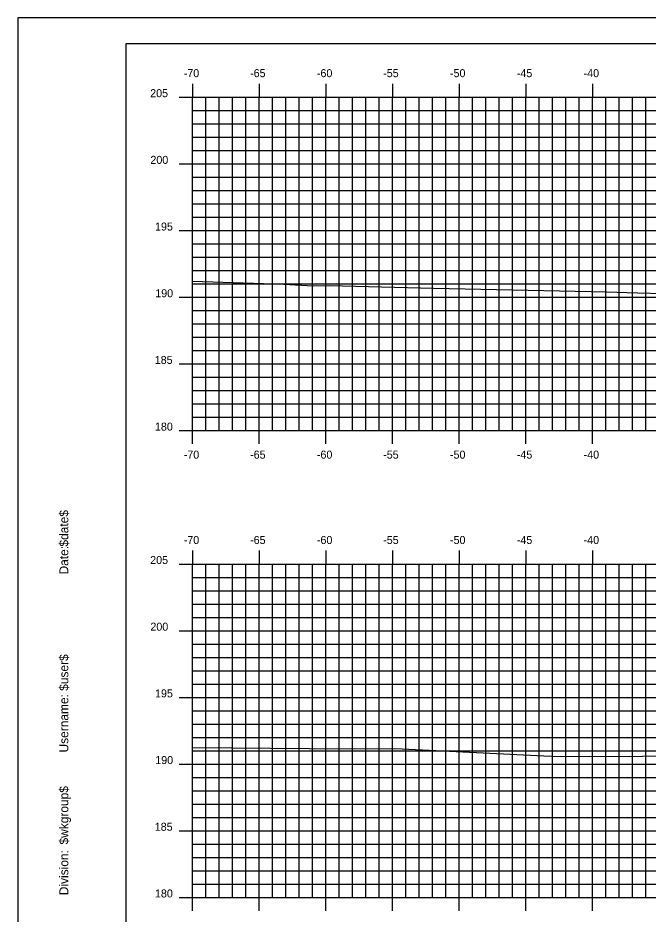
# Model space of a CAD drawing. Extents: x 1723543 to 1723714, y 458501 to 458611.
# Drawn here: x 1723542.7 to 1723589.9, y 458544 to 458611.2 of the extents above; entities that cross this region are included whole.
import ezdxf

# ---------------------------------------------------------------- set-up
doc = ezdxf.new("R2010")
doc.units = 0
for name, color, linetype in [('BORDER', 7, 'Continuous'), ('H_V ANNOTATION', 7, 'Continuous'), ('MAJOR', 7, 'Continuous'), ('MINOR', 7, 'Continuous'), ('PLOT BOUNDARY', 7, 'Continuous'), ('S_Roadway_Centerline', 7, 'Continuous')]:
    doc.layers.add(name, color=color, linetype=linetype)

msp = doc.modelspace()

# ---------------------------------------------------------------- linework, layer by layer
at = {"layer": 'BORDER'}
msp.add_lwpolyline([(1723550.786, 458504.254), (1723710.786, 458504.254), (1723710.786, 458609.254), (1723550.786, 458609.254)], close=True, dxfattribs=at)
at = {"layer": 'MAJOR'}
for p, q in [((1723555.785, 458606.256), (1723555.785, 458605.254)), ((1723560.785, 458606.256), (1723560.785, 458605.254)), ((1723565.785, 458606.256), (1723565.785, 458605.254)), ((1723570.785, 458606.256), (1723570.785, 458605.254)), ((1723575.785, 458606.256), (1723575.785, 458605.254)), ((1723580.785, 458606.256), (1723580.785, 458605.254)), ((1723585.785, 458606.256), (1723585.785, 458605.254)), ((1723554.783, 458605.254), (1723555.785, 458605.254)), ((1723555.785, 458605.254), (1723695.785, 458605.254)), ((1723555.785, 458580.254), (1723555.785, 458605.254)), ((1723555.785, 458580.254), (1723555.785, 458605.254)), ((1723555.785, 458605.254), (1723695.785, 458605.254)), ((1723560.785, 458580.254), (1723560.785, 458605.254)), ((1723565.785, 458580.254), (1723565.785, 458605.254)), ((1723570.785, 458580.254), (1723570.785, 458605.254)), ((1723575.785, 458580.254), (1723575.785, 458605.254)), ((1723580.785, 458580.254), (1723580.785, 458605.254)), ((1723585.785, 458580.254), (1723585.785, 458605.254)), ((1723554.783, 458600.254), (1723555.785, 458600.254)), ((1723555.785, 458600.254), (1723695.785, 458600.254)), ((1723554.783, 458595.254), (1723555.785, 458595.254)), ((1723555.785, 458595.254), (1723695.785, 458595.254)), ((1723554.783, 458590.254), (1723555.785, 458590.254)), ((1723555.785, 458590.254), (1723695.785, 458590.254)), ((1723554.783, 458585.254), (1723555.785, 458585.254)), ((1723555.785, 458585.254), (1723695.785, 458585.254)), ((1723554.783, 458580.254), (1723555.785, 458580.254)), ((1723555.785, 458580.254), (1723695.785, 458580.254)), ((1723555.785, 458580.254), (1723695.785, 458580.254)), ((1723555.785, 458579.252), (1723555.785, 458580.254)), ((1723560.785, 458579.252), (1723560.785, 458580.254)), ((1723565.785, 458579.252), (1723565.785, 458580.254)), ((1723570.785, 458579.252), (1723570.785, 458580.254)), ((1723575.785, 458579.252), (1723575.785, 458580.254)), ((1723580.785, 458579.252), (1723580.785, 458580.254)), ((1723585.785, 458579.252), (1723585.785, 458580.254)), ((1723555.785, 458571.256), (1723555.785, 458570.254)), ((1723560.785, 458571.256), (1723560.785, 458570.254)), ((1723565.785, 458571.256), (1723565.785, 458570.254)), ((1723570.785, 458571.256), (1723570.785, 458570.254)), ((1723575.785, 458571.256), (1723575.785, 458570.254)), ((1723580.785, 458571.256), (1723580.785, 458570.254)), ((1723585.785, 458571.256), (1723585.785, 458570.254)), ((1723554.783, 458570.254), (1723555.785, 458570.254)), ((1723555.785, 458570.254), (1723695.785, 458570.254)), ((1723555.785, 458545.254), (1723555.785, 458570.254)), ((1723555.785, 458545.254), (1723555.785, 458570.254)), ((1723555.785, 458570.254), (1723695.785, 458570.254)), ((1723560.785, 458545.254), (1723560.785, 458570.254)), ((1723565.785, 458545.254), (1723565.785, 458570.254)), ((1723570.785, 458545.254), (1723570.785, 458570.254)), ((1723575.785, 458545.254), (1723575.785, 458570.254)), ((1723580.785, 458545.254), (1723580.785, 458570.254)), ((1723585.785, 458545.254), (1723585.785, 458570.254)), ((1723554.783, 458565.254), (1723555.785, 458565.254)), ((1723555.785, 458565.254), (1723695.785, 458565.254)), ((1723554.783, 458560.254), (1723555.785, 458560.254)), ((1723555.785, 458560.254), (1723695.785, 458560.254)), ((1723554.783, 458555.254), (1723555.785, 458555.254)), ((1723555.785, 458555.254), (1723695.785, 458555.254)), ((1723554.783, 458550.254), (1723555.785, 458550.254)), ((1723555.785, 458550.254), (1723695.785, 458550.254)), ((1723554.783, 458545.254), (1723555.785, 458545.254)), ((1723555.785, 458545.254), (1723695.785, 458545.254)), ((1723555.785, 458545.254), (1723695.785, 458545.254)), ((1723555.785, 458544.252), (1723555.785, 458545.254)), ((1723560.785, 458544.252), (1723560.785, 458545.254)), ((1723565.785, 458544.252), (1723565.785, 458545.254)), ((1723570.785, 458544.252), (1723570.785, 458545.254)), ((1723575.785, 458544.252), (1723575.785, 458545.254)), ((1723580.785, 458544.252), (1723580.785, 458545.254)), ((1723585.785, 458544.252), (1723585.785, 458545.254))]:
    msp.add_line(p, q, dxfattribs=at)
at = {"layer": 'MINOR'}
for p, q in [((1723556.785, 458580.254), (1723556.785, 458605.254)), ((1723557.785, 458580.254), (1723557.785, 458605.254)), ((1723558.785, 458580.254), (1723558.785, 458605.254)), ((1723559.785, 458580.254), (1723559.785, 458605.254)), ((1723561.785, 458580.254), (1723561.785, 458605.254)), ((1723562.785, 458580.254), (1723562.785, 458605.254)), ((1723563.785, 458580.254), (1723563.785, 458605.254)), ((1723564.785, 458580.254), (1723564.785, 458605.254)), ((1723566.785, 458580.254), (1723566.785, 458605.254)), ((1723567.785, 458580.254), (1723567.785, 458605.254)), ((1723568.785, 458580.254), (1723568.785, 458605.254)), ((1723569.785, 458580.254), (1723569.785, 458605.254)), ((1723571.785, 458580.254), (1723571.785, 458605.254)), ((1723572.785, 458580.254), (1723572.785, 458605.254)), ((1723573.785, 458580.254), (1723573.785, 458605.254)), ((1723574.785, 458580.254), (1723574.785, 458605.254)), ((1723576.785, 458580.254), (1723576.785, 458605.254)), ((1723577.785, 458580.254), (1723577.785, 458605.254)), ((1723578.785, 458580.254), (1723578.785, 458605.254)), ((1723579.785, 458580.254), (1723579.785, 458605.254)), ((1723581.785, 458580.254), (1723581.785, 458605.254)), ((1723582.785, 458580.254), (1723582.785, 458605.254)), ((1723583.785, 458580.254), (1723583.785, 458605.254)), ((1723584.785, 458580.254), (1723584.785, 458605.254)), ((1723586.785, 458580.254), (1723586.785, 458605.254)), ((1723587.785, 458580.254), (1723587.785, 458605.254)), ((1723588.785, 458580.254), (1723588.785, 458605.254)), ((1723589.785, 458580.254), (1723589.785, 458605.254)), ((1723555.785, 458604.254), (1723695.785, 458604.254)), ((1723555.785, 458604.254), (1723556.787, 458604.254)), ((1723555.785, 458603.254), (1723695.785, 458603.254)), ((1723555.785, 458603.254), (1723556.787, 458603.254)), ((1723555.785, 458602.254), (1723695.785, 458602.254)), ((1723555.785, 458602.254), (1723556.787, 458602.254)), ((1723555.785, 458601.254), (1723695.785, 458601.254)), ((1723555.785, 458601.254), (1723556.787, 458601.254)), ((1723555.785, 458599.254), (1723695.785, 458599.254)), ((1723555.785, 458599.254), (1723556.787, 458599.254)), ((1723555.785, 458598.254), (1723695.785, 458598.254)), ((1723555.785, 458598.254), (1723556.787, 458598.254)), ((1723555.785, 458597.254), (1723695.785, 458597.254)), ((1723555.785, 458597.254), (1723556.787, 458597.254)), ((1723555.785, 458596.254), (1723695.785, 458596.254)), ((1723555.785, 458596.254), (1723556.787, 458596.254)), ((1723555.785, 458594.254), (1723695.785, 458594.254)), ((1723555.785, 458594.254), (1723556.787, 458594.254)), ((1723555.785, 458593.254), (1723695.785, 458593.254)), ((1723555.785, 458593.254), (1723556.787, 458593.254)), ((1723555.785, 458592.254), (1723695.785, 458592.254)), ((1723555.785, 458592.254), (1723556.787, 458592.254)), ((1723555.785, 458591.254), (1723695.785, 458591.254)), ((1723555.785, 458591.254), (1723556.787, 458591.254)), ((1723555.785, 458589.254), (1723695.785, 458589.254)), ((1723555.785, 458589.254), (1723556.787, 458589.254)), ((1723555.785, 458588.254), (1723695.785, 458588.254)), ((1723555.785, 458588.254), (1723556.787, 458588.254)), ((1723555.785, 458587.254), (1723695.785, 458587.254)), ((1723555.785, 458587.254), (1723556.787, 458587.254)), ((1723555.785, 458586.254), (1723695.785, 458586.254)), ((1723555.785, 458586.254), (1723556.787, 458586.254)), ((1723555.785, 458584.254), (1723695.785, 458584.254)), ((1723555.785, 458584.254), (1723556.787, 458584.254)), ((1723555.785, 458583.254), (1723695.785, 458583.254)), ((1723555.785, 458583.254), (1723556.787, 458583.254)), ((1723555.785, 458582.254), (1723695.785, 458582.254)), ((1723555.785, 458582.254), (1723556.787, 458582.254)), ((1723555.785, 458581.254), (1723695.785, 458581.254)), ((1723555.785, 458581.254), (1723556.787, 458581.254)), ((1723556.785, 458545.254), (1723556.785, 458570.254)), ((1723557.785, 458545.254), (1723557.785, 458570.254)), ((1723558.785, 458545.254), (1723558.785, 458570.254)), ((1723559.785, 458545.254), (1723559.785, 458570.254)), ((1723561.785, 458545.254), (1723561.785, 458570.254)), ((1723562.785, 458545.254), (1723562.785, 458570.254)), ((1723563.785, 458545.254), (1723563.785, 458570.254)), ((1723564.785, 458545.254), (1723564.785, 458570.254)), ((1723566.785, 458545.254), (1723566.785, 458570.254)), ((1723567.785, 458545.254), (1723567.785, 458570.254)), ((1723568.785, 458545.254), (1723568.785, 458570.254)), ((1723569.785, 458545.254), (1723569.785, 458570.254)), ((1723571.785, 458545.254), (1723571.785, 458570.254)), ((1723572.785, 458545.254), (1723572.785, 458570.254)), ((1723573.785, 458545.254), (1723573.785, 458570.254)), ((1723574.785, 458545.254), (1723574.785, 458570.254)), ((1723576.785, 458545.254), (1723576.785, 458570.254)), ((1723577.785, 458545.254), (1723577.785, 458570.254)), ((1723578.785, 458545.254), (1723578.785, 458570.254)), ((1723579.785, 458545.254), (1723579.785, 458570.254)), ((1723581.785, 458545.254), (1723581.785, 458570.254)), ((1723582.785, 458545.254), (1723582.785, 458570.254)), ((1723583.785, 458545.254), (1723583.785, 458570.254)), ((1723584.785, 458545.254), (1723584.785, 458570.254)), ((1723586.785, 458545.254), (1723586.785, 458570.254)), ((1723587.785, 458545.254), (1723587.785, 458570.254)), ((1723588.785, 458545.254), (1723588.785, 458570.254)), ((1723589.785, 458545.254), (1723589.785, 458570.254)), ((1723555.785, 458569.254), (1723695.785, 458569.254)), ((1723555.785, 458569.254), (1723556.787, 458569.254)), ((1723555.785, 458568.254), (1723695.785, 458568.254)), ((1723555.785, 458568.254), (1723556.787, 458568.254)), ((1723555.785, 458567.254), (1723695.785, 458567.254)), ((1723555.785, 458567.254), (1723556.787, 458567.254)), ((1723555.785, 458566.254), (1723695.785, 458566.254)), ((1723555.785, 458566.254), (1723556.787, 458566.254)), ((1723555.785, 458564.254), (1723695.785, 458564.254)), ((1723555.785, 458564.254), (1723556.787, 458564.254)), ((1723555.785, 458563.254), (1723695.785, 458563.254)), ((1723555.785, 458563.254), (1723556.787, 458563.254)), ((1723555.785, 458562.254), (1723695.785, 458562.254)), ((1723555.785, 458562.254), (1723556.787, 458562.254)), ((1723555.785, 458561.254), (1723695.785, 458561.254)), ((1723555.785, 458561.254), (1723556.787, 458561.254)), ((1723555.785, 458559.254), (1723695.785, 458559.254)), ((1723555.785, 458559.254), (1723556.787, 458559.254)), ((1723555.785, 458558.254), (1723695.785, 458558.254)), ((1723555.785, 458558.254), (1723556.787, 458558.254)), ((1723555.785, 458557.254), (1723695.785, 458557.254)), ((1723555.785, 458557.254), (1723556.787, 458557.254)), ((1723555.785, 458556.254), (1723695.785, 458556.254)), ((1723555.785, 458556.254), (1723556.787, 458556.254)), ((1723555.785, 458554.254), (1723695.785, 458554.254)), ((1723555.785, 458554.254), (1723556.787, 458554.254)), ((1723555.785, 458553.254), (1723695.785, 458553.254)), ((1723555.785, 458553.254), (1723556.787, 458553.254)), ((1723555.785, 458552.254), (1723695.785, 458552.254)), ((1723555.785, 458552.254), (1723556.787, 458552.254)), ((1723555.785, 458551.254), (1723695.785, 458551.254)), ((1723555.785, 458551.254), (1723556.787, 458551.254)), ((1723555.785, 458549.254), (1723695.785, 458549.254)), ((1723555.785, 458549.254), (1723556.787, 458549.254)), ((1723555.785, 458548.254), (1723695.785, 458548.254)), ((1723555.785, 458548.254), (1723556.787, 458548.254)), ((1723555.785, 458547.254), (1723695.785, 458547.254)), ((1723555.785, 458547.254), (1723556.787, 458547.254)), ((1723555.785, 458546.254), (1723695.785, 458546.254)), ((1723555.785, 458546.254), (1723556.787, 458546.254))]:
    msp.add_line(p, q, dxfattribs=at)
at = {"layer": 'PLOT BOUNDARY'}
msp.add_lwpolyline([(1723542.692, 458501.195), (1723712.692, 458501.195), (1723712.692, 458611.195), (1723542.692, 458611.195)], close=True, dxfattribs=at)
at = {"layer": 'S_Roadway_Centerline'}
for points in [[(1723555.785, 458591.47), (1723562.634, 458591.225), (1723564.833, 458591.119), (1723566.056, 458591.128), (1723573.85, 458590.931), (1723586.854, 458590.649), (1723589.146, 458590.577), (1723593.094, 458590.494), (1723606.299, 458590.024), (1723622.288, 458589.703), (1723624.211, 458589.684), (1723625.504, 458589.67), (1723636.39, 458589.225), (1723646.889, 458588.895), (1723648.382, 458588.881), (1723666.137, 458588.667), (1723680.866, 458588.185), (1723683.212, 458588.086), (1723684.599, 458588.051), (1723694.44, 458587.568), (1723695.785, 458587.47)], [(1723555.785, 458556.489), (1723564.545, 458556.413), (1723571.514, 458556.395), (1723582.117, 458555.861), (1723583.488, 458555.828), (1723595.581, 458555.866), (1723602.294, 458555.786), (1723607.123, 458555.553), (1723613.878, 458555.293), (1723623.634, 458555.001), (1723642.551, 458554.449), (1723642.611, 458554.446), (1723642.654, 458554.445), (1723642.863, 458554.44), (1723662.248, 458553.975), (1723671.582, 458553.786), (1723678.391, 458553.664), (1723682.357, 458553.433), (1723689.959, 458553.132), (1723695.785, 458552.954)]]:
    msp.add_lwpolyline(points, dxfattribs=at)

# ---------------------------------------------------------------- texts
at = {"layer": 'BORDER'}
for s, p in [('$date$', (1723546.47, 458571.559)), ('Date:', (1723546.47, 458569.471)), ('$user$', (1723546.47, 458560.746)), ('Username:', (1723546.47, 458556.122)), ('$wkgroup$', (1723546.47, 458549.224)), ('Division:', (1723546.47, 458545.42))]:
    msp.add_text(s, height=0.6696, rotation=90, dxfattribs=at).set_placement(p)
at = {"layer": 'H_V ANNOTATION'}
for s, p in [('-70', (1723555.127, 458606.754)), ('-65', (1723560.103, 458606.754)), ('-60', (1723565.111, 458606.754)), ('-55', (1723570.082, 458606.754)), ('-50', (1723575.09, 458606.754)), ('-45', (1723580.103, 458606.754)), ('-40', (1723585.111, 458606.754)), ('205', (1723552.61, 458605.254)), ('200', (1723552.626, 458600.254)), ('195', (1723552.974, 458595.254)), ('190', (1723552.99, 458590.254)), ('185', (1723552.953, 458585.254)), ('180', (1723552.969, 458580.254)), ('-70', (1723555.127, 458578.154)), ('-65', (1723560.103, 458578.154)), ('-60', (1723565.111, 458578.154)), ('-55', (1723570.082, 458578.154)), ('-50', (1723575.09, 458578.154)), ('-45', (1723580.103, 458578.154)), ('-40', (1723585.111, 458578.154)), ('-70', (1723555.127, 458571.754)), ('-65', (1723560.103, 458571.754)), ('-60', (1723565.111, 458571.754)), ('-55', (1723570.082, 458571.754)), ('-50', (1723575.09, 458571.754)), ('-45', (1723580.103, 458571.754)), ('-40', (1723585.111, 458571.754)), ('205', (1723552.61, 458570.254)), ('200', (1723552.626, 458565.254)), ('195', (1723552.974, 458560.254)), ('190', (1723552.99, 458555.254)), ('185', (1723552.953, 458550.254)), ('180', (1723552.969, 458545.254))]:
    msp.add_text(s, height=0.6, dxfattribs=at).set_placement(p)
at = {"layer": 'MAJOR'}
for p in [(1723555.781, 458580.254), (1723555.781, 458545.254)]:
    msp.add_text('-', height=0.006, dxfattribs=at).set_placement(p)

doc.saveas('drawing.dxf')
